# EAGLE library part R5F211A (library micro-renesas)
16-BIT SINGLE-CHIP MICROCOMPUTER M16C FAMILY / R8C/Tiny SERIES Source: Renesas .. rej09b0252_r8c1a1bhm.pdf
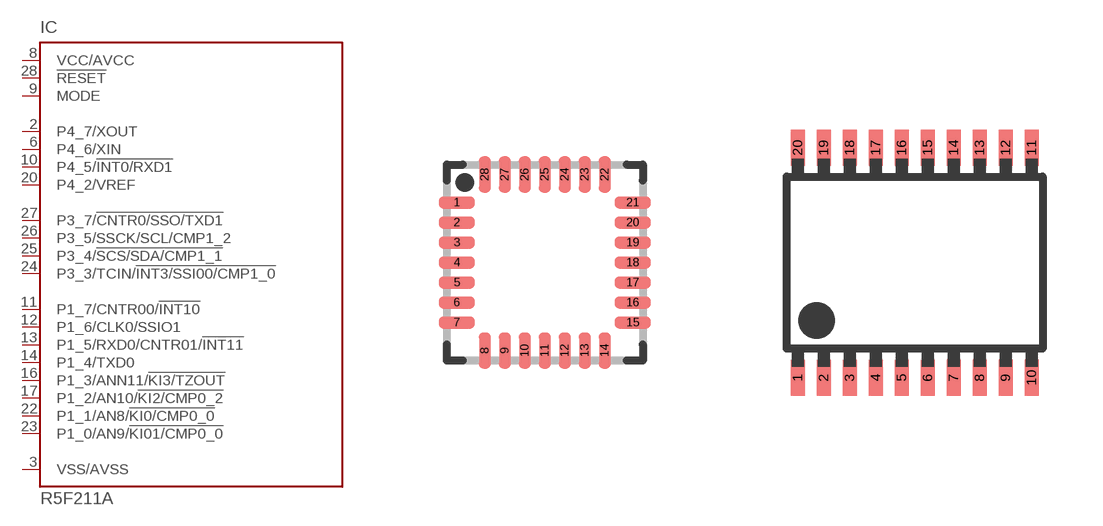
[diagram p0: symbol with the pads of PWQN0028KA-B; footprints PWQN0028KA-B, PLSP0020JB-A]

Designator prefix IC

## R5F211A2NP (OC_FARNELL: unknown; OC_NEWARK: unknown), R5F211A3NP (OC_FARNELL: unknown; OC_NEWARK: unknown), R5F211A4NP (OC_FARNELL: unknown; OC_NEWARK: unknown)  [PWQN0028KA-B]
2  P4_7/XOUT
3  VSS/AVSS  in
6  P4_6/XIN
8  VCC/AVCC  in
9  MODE  in
10  P4_5/!INT0/RXD1
11  P1_7/CNTR00/!INT10
12  P1_6/CLK0/SSIO1
13  P1_5/RXD0/CNTR01/!INT11
14  P1_4/TXD0
16  P1_3/ANN11/!KI3/TZOUT
17  P1_2/AN10/!KI2/CMP0_2
20  P4_2/VREF  in
22  P1_1/AN8/!KI0/CMP0_0
23  P1_0/AN9/!KI01/CMP0_0
24  P3_3/TCIN/!INT3/SSI00/CMP1_0
25  P3_4/!SCS/SDA/CMP1_1
26  P3_5/SSCK/SCL/CMP1_2
27  P3_7/!CNTR0/SSO/TXD1
28  !RESET  in

## R5F211A1SP (OC_FARNELL: unknown; OC_NEWARK: unknown), R5F211A1DSP (OC_FARNELL: unknown; OC_NEWARK: unknown), R5F211A2SP (OC_FARNELL: unknown; OC_NEWARK: unknown), R5F211A2DSP (OC_FARNELL: unknown; OC_NEWARK: unknown), R5F211A3SP (OC_FARNELL: unknown; OC_NEWARK: unknown), R5F211A3DSP (OC_FARNELL: unknown; OC_NEWARK: unknown), R5F211A4SP (MPN: R5F211A4SP#U0; OC_FARNELL: 1677765; OC_NEWARK: 40P3229), R5F211A4DSP (OC_FARNELL: unknown; OC_NEWARK: unknown)  [PLSP0020JB-A]
1  P3_5/SSCK/SCL/CMP1_2
2  P3_7/!CNTR0/SSO/TXD1
3  !RESET  in
4  P4_7/XOUT
5  VSS/AVSS  in
6  P4_6/XIN
7  VCC/AVCC  in
8  MODE  in
9  P4_5/!INT0/RXD1
10  P1_7/CNTR00/!INT10
11  P1_6/CLK0/SSIO1
12  P1_5/RXD0/CNTR01/!INT11
13  P1_4/TXD0
14  P1_3/ANN11/!KI3/TZOUT
15  P1_2/AN10/!KI2/CMP0_2
16  P4_2/VREF  in
17  P1_1/AN8/!KI0/CMP0_0
18  P1_0/AN9/!KI01/CMP0_0
19  P3_3/TCIN/!INT3/SSI00/CMP1_0
20  P3_4/!SCS/SDA/CMP1_1

## R5F211A1DD (OC_FARNELL: unknown; OC_NEWARK: unknown), R5F211A2DD (OC_FARNELL: unknown; OC_NEWARK: unknown), R5F211A3DD (OC_FARNELL: unknown; OC_NEWARK: unknown), R5F211A4DD (OC_FARNELL: unknown; OC_NEWARK: unknown)  [PRDP0020BA-A]
Pads as for PLSP0020JB-A

## Footprint PWQN0028KA-B (pad centres in mm)
P-HWQFN28-5x5-0.50 Source: Renesas .. rej09b0252_r8c1a1bhm.pdf
smd 0.9 x 0.3: 1 -2.2,1.5; 2 -2.2,1; 3 -2.2,0.5; 4 -2.2,0; 5 -2.2,-0.5; 6 -2.2,-1; 7 -2.2,-1.5; 15 2.2,-1.5; 16 2.2,-1; 17 2.2,-0.5; 18 2.2,0; 19 2.2,0.5; 20 2.2,1; 21 2.2,1.5
smd 0.3 x 0.9: 8 -1.5,-2.2; 9 -1,-2.2; 10 -0.5,-2.2; 11 0,-2.2; 12 0.5,-2.2; 13 1,-2.2; 14 1.5,-2.2; 22 1.5,2.2; 23 1,2.2; 24 0.5,2.2; 25 0,2.2; 26 -0.5,2.2; 27 -1,2.2; 28 -1.5,2.2

## Footprint PLSP0020JB-A (pad centres in mm)
P-LSSOP20-4.4x6.5-0.65 Source: Renesas .. rej09b0252_r8c1a1bhm.pdf
smd 0.35 x 0.9: 1 -2.925,-2.875; 2 -2.275,-2.875; 3 -1.625,-2.875; 4 -0.975,-2.875; 5 -0.325,-2.875; 6 0.325,-2.875; 7 0.975,-2.875; 8 1.625,-2.875; 9 2.275,-2.875; 10 2.925,-2.875; 11 2.925,2.875; 12 2.275,2.875; 13 1.625,2.875; 14 0.975,2.875; 15 0.325,2.875; 16 -0.325,2.875; 17 -0.975,2.875; 18 -1.625,2.875; 19 -2.275,2.875; 20 -2.925,2.875

## Footprint PRDP0020BA-A (pad centres in mm)
P-SDIP20-6.3x19-1.78 Source: Renesas .. rej09b0252_r8c1a1bhm.pdf
drill 0.8 pad 1.27 round: 1 -8.001,-3.81; 2 -6.223,-3.81; 3 -4.445,-3.81; 4 -2.667,-3.81; 5 -0.889,-3.81; 6 0.889,-3.81; 7 2.667,-3.81; 8 4.445,-3.81; 9 6.223,-3.81; 10 8.001,-3.81; 11 8.001,3.81; 12 6.223,3.81; 13 4.445,3.81; 14 2.667,3.81; 15 0.889,3.81; 16 -0.889,3.81; 17 -2.667,3.81; 18 -4.445,3.81; 19 -6.223,3.81; 20 -8.001,3.81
